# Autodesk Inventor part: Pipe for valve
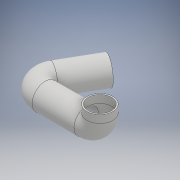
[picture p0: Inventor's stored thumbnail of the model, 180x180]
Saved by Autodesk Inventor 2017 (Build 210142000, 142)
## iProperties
Created: 2020-04
Part Number: Pipe for valve
Material: Generic
Document SubType Name: Modeling
Designer: user
Density: 1 g/cm^3
Appearance: Default
Author: user
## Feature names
1. Sweep1
## Parameters: d0 = 15.96 mm, d1 = 42.28 mm, d4 = 60 deg, d6 = 1 mm, d7 = 0, d8 = 0
